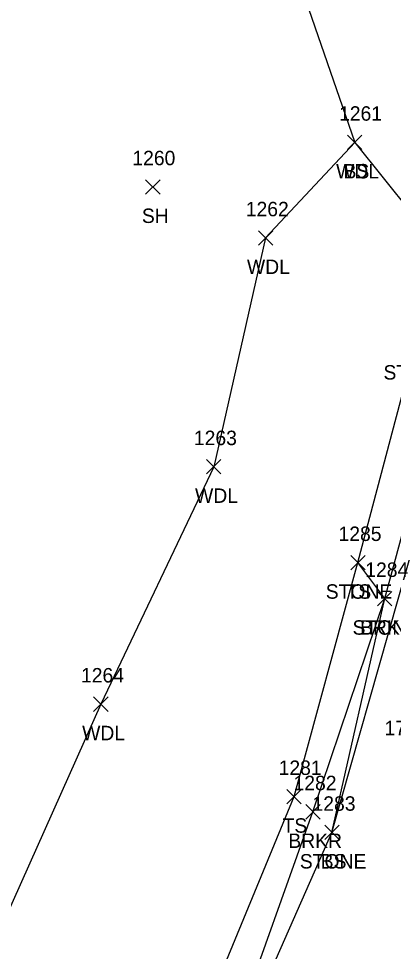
# Model space of a CAD drawing. Extents: x 1651305 to 1654558, y 539481 to 548441.
# Drawn here: x 1654251.1 to 1654303, y 544544.9 to 544674.1 of the extents above; entities that cross this region are included whole.
import ezdxf

# ---------------------------------------------------------------- set-up
doc = ezdxf.new("R2010")
doc.units = 0
for name, color, linetype in [('L_A', 7, 'Continuous'), ('L_I', 7, 'Continuous'), ('L_TIC', 7, 'Continuous'), ('LASF', 7, 'Continuous'), ('LAWA', 7, 'Continuous'), ('LAWE', 7, 'Continuous'), ('LELB', 7, 'Continuous')]:
    doc.layers.add(name, color=color, linetype=linetype)

msp = doc.modelspace()

# ---------------------------------------------------------------- linework, layer by layer
at = {"layer": 'L_TIC'}
for points in [[(1654296.61, 544655.98), (1654298.61, 544657.98)], [(1654298.61, 544655.98), (1654296.61, 544657.98)], [(1654296.61, 544655.98), (1654298.61, 544657.98)], [(1654298.61, 544655.98), (1654296.61, 544657.98)], [(1654268.66, 544649.81), (1654270.66, 544651.81)], [(1654270.66, 544649.81), (1654268.66, 544651.81)], [(1654284.27, 544642.74), (1654286.27, 544644.74)], [(1654286.27, 544642.74), (1654284.27, 544644.74)], [(1654277.09, 544611.04), (1654279.09, 544613.04)], [(1654279.09, 544611.04), (1654277.09, 544613.04)], [(1654297.06, 544597.76), (1654299.06, 544599.76)], [(1654299.06, 544597.76), (1654297.06, 544599.76)], [(1654297.06, 544597.76), (1654299.06, 544599.76)], [(1654299.06, 544597.76), (1654297.06, 544599.76)], [(1654300.76, 544592.78), (1654302.76, 544594.78)], [(1654302.76, 544592.78), (1654300.76, 544594.78)], [(1654300.76, 544592.78), (1654302.76, 544594.78)], [(1654302.76, 544592.78), (1654300.76, 544594.78)], [(1654261.46, 544578.16), (1654263.46, 544580.16)], [(1654263.46, 544578.16), (1654261.46, 544580.16)], [(1654288.21, 544565.35), (1654290.21, 544567.35)], [(1654290.21, 544565.35), (1654288.21, 544567.35)], [(1654290.83, 544563.24), (1654292.83, 544565.24)], [(1654292.83, 544563.24), (1654290.83, 544565.24)], [(1654293.46, 544560.39), (1654295.46, 544562.39)], [(1654295.46, 544560.39), (1654293.46, 544562.39)], [(1654293.46, 544560.39), (1654295.46, 544562.39)], [(1654295.46, 544560.39), (1654293.46, 544562.39)]]:
    msp.add_lwpolyline(points, dxfattribs=at)
at = {"layer": 'LASF'}
msp.add_lwpolyline([(1654294.46, 544561.39), (1654301.76, 544593.78), (1654298.06, 544598.76), (1654306.05, 544629.12), (1654309.41, 544642.27), (1654312.66, 544656.56)], dxfattribs=at)
at = {"layer": 'LAWA'}
msp.add_lwpolyline([(1654297.61, 544656.98), (1654285.27, 544643.74), (1654278.09, 544612.04), (1654262.46, 544579.16), (1654244.7, 544539.43), (1654219.21, 544486.29)], dxfattribs=at)
at = {"layer": 'LAWE'}
msp.add_lwpolyline([(1654242.51, 544465.97), (1654256.87, 544483.55), (1654283.12, 544539.87), (1654291.83, 544564.24), (1654301.76, 544593.78), (1654310.98, 544627.69), (1654314.7, 544654.65), (1654333.85, 544703.3), (1654340.89, 544719.25), (1654343, 544745.95), (1654343.54, 544777), (1654341.26, 544814.62), (1654342.7, 544842.64), (1654342.65, 544866.8)], dxfattribs=at)
at = {"layer": 'LELB'}
for points in [[(1654177.71, 544985.41), (1654186.4, 544960.29), (1654198.08, 544925.07), (1654208.78, 544901.64), (1654231.34, 544847.61), (1654245.85, 544816.46), (1654261.74, 544769.7), (1654274.87, 544730.83), (1654284.44, 544695.19), (1654297.61, 544656.98), (1654309.41, 544642.27)], [(1654243.66, 544463.61), (1654257.64, 544478.05), (1654284.35, 544538.42), (1654294.46, 544561.39), (1654312.81, 544626.03), (1654318.85, 544643.27), (1654339.17, 544696.64), (1654344.53, 544715.65), (1654345.59, 544746.87), (1654345.75, 544776.72), (1654344.63, 544815.2), (1654344.44, 544841.84), (1654343.53, 544866.97)], [(1654236.19, 544472.4), (1654254.47, 544503.5), (1654271.69, 544523.85), (1654289.21, 544566.35), (1654298.06, 544598.76)]]:
    msp.add_lwpolyline(points, dxfattribs=at)

# ---------------------------------------------------------------- texts
at = {"layer": 'L_A'}
for s, p in [('WDL', (1654295.03, 544651.98)), ('BS', (1654296.06, 544651.98)), ('SH', (1654268.15, 544645.81)), ('WDL', (1654282.69, 544638.74)), ('STONE', (1654301.59, 544624.12)), ('WDL', (1654275.51, 544607.04)), ('STONE', (1654293.6, 544593.76)), ('TS', (1654296.47, 544593.76)), ('STONE', (1654297.31, 544588.78)), ('BRKR', (1654298.35, 544588.78)), ('WDL', (1654259.88, 544574.16)), ('TS', (1654287.62, 544561.35)), ('BRKR', (1654288.42, 544559.24)), ('STONE', (1654290.01, 544556.39)), ('BS', (1654292.9, 544556.39))]:
    msp.add_text(s, height=2, dxfattribs=at).set_placement(p)
at = {"layer": 'L_I'}
for s, p in [('1261', (1654295.44, 544659.98)), ('1261', (1654295.44, 544659.98)), ('1260', (1654266.83, 544653.81)), ('1262', (1654282.53, 544646.74)), ('1263', (1654275.35, 544615.04)), ('1285', (1654295.37, 544601.76)), ('1285', (1654295.37, 544601.76)), ('1284', (1654299.07, 544596.78)), ('1284', (1654299.07, 544596.78)), ('1264', (1654259.72, 544582.16)), ('1720', (1654301.74, 544574.86)), ('1281', (1654287.08, 544569.35)), ('1282', (1654289.14, 544567.24)), ('1283', (1654291.77, 544564.39)), ('1283', (1654291.77, 544564.39))]:
    msp.add_text(s, height=2, dxfattribs=at).set_placement(p)

doc.saveas('drawing.dxf')
